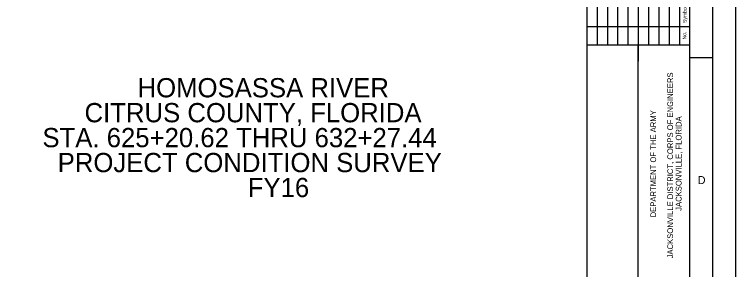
# Model space of a CAD drawing. Extents: x 384865 to 516869, y 1553900 to 1655899.
# Drawn here: x 469592 to 516865, y 1607032 to 1623741 of the extents above; entities that cross this region are included whole.
import ezdxf

# ---------------------------------------------------------------- set-up
doc = ezdxf.new("R2010")
doc.units = 0
for name, color, linetype in [('G-ANNO-NPLT', 7, 'Continuous'), ('G-ANNO-TEXT-TTLB', 7, 'Continuous'), ('G-ANNO-TTLB', 7, 'Continuous'), ('V-ANNO-TEXT', 7, 'Continuous')]:
    doc.layers.add(name, color=color, linetype=linetype)

msp = doc.modelspace()

# ---------------------------------------------------------------- linework, layer by layer
at = {"layer": 'G-ANNO-NPLT'}
msp.add_lwpolyline([(384865, 1655899), (516865, 1655899), (516865, 1553900), (384865, 1553900)], close=True, dxfattribs=at)
at = {"layer": 'G-ANNO-TTLB'}
for p, q in [((507114, 1652899), (507114, 1556900)), ((507784, 1646889), (507784, 1621751)), ((508459, 1646889), (508459, 1621751)), ((509134, 1646889), (509134, 1621751)), ((509809, 1646889), (509809, 1621751)), ((510484, 1646889), (510484, 1621751)), ((511159, 1646889), (511159, 1621751)), ((511834, 1646889), (511834, 1621751)), ((512509, 1646889), (512509, 1621751)), ((513184, 1646889), (513184, 1621751)), ((507115, 1622947), (513865, 1622946)), ((507115, 1621751), (513865, 1621751)), ((510470, 1595964), (510490, 1621751)), ((510490, 1621751), (510489, 1620689)), ((515365, 1620895), (513865, 1620895))]:
    msp.add_line(p, q, dxfattribs=at)
for points in [[(386365, 1555400), (515365, 1555400), (515365, 1654399), (386365, 1654399)], [(513865, 1652899), (390115, 1652899), (390115, 1556900), (513865, 1556900)]]:
    msp.add_lwpolyline(points, close=True, dxfattribs=at)

# ---------------------------------------------------------------- texts
at = {"layer": 'G-ANNO-TEXT-TTLB'}
for s, height, p in [('Symbol', 240, (513657, 1623182)), ('No.', 240, (513627, 1622099)), ('JACKSONVILLE DISTRICT, CORPS OF ENGINEERS', 375, (512766, 1607765)), ('DEPARTMENT OF THE ARMY', 375, (511656, 1610447)), ('JACKSONVILLE, FLORIDA', 375, (513321, 1610881))]:
    msp.add_text(s, height=height, rotation=90, dxfattribs=at).set_placement(p)
at = {"layer": 'G-ANNO-TTLB'}
msp.add_text('D', height=525, dxfattribs=at).set_placement((514385, 1612631))
at = {"layer": 'V-ANNO-TEXT'}
for s, p in [('HOMOSASSA RIVER', (477665, 1618311)), ('CITRUS COUNTY, FLORIDA', (474189, 1616678)), ('STA. 625+20.62 THRU 632+27.44', (471428, 1615044)), ('PROJECT CONDITION SURVEY', (472429, 1613411)), ('FY16', (484888, 1611777))]:
    msp.add_text(s, height=1260, dxfattribs=at).set_placement(p)

doc.saveas('drawing.dxf')
